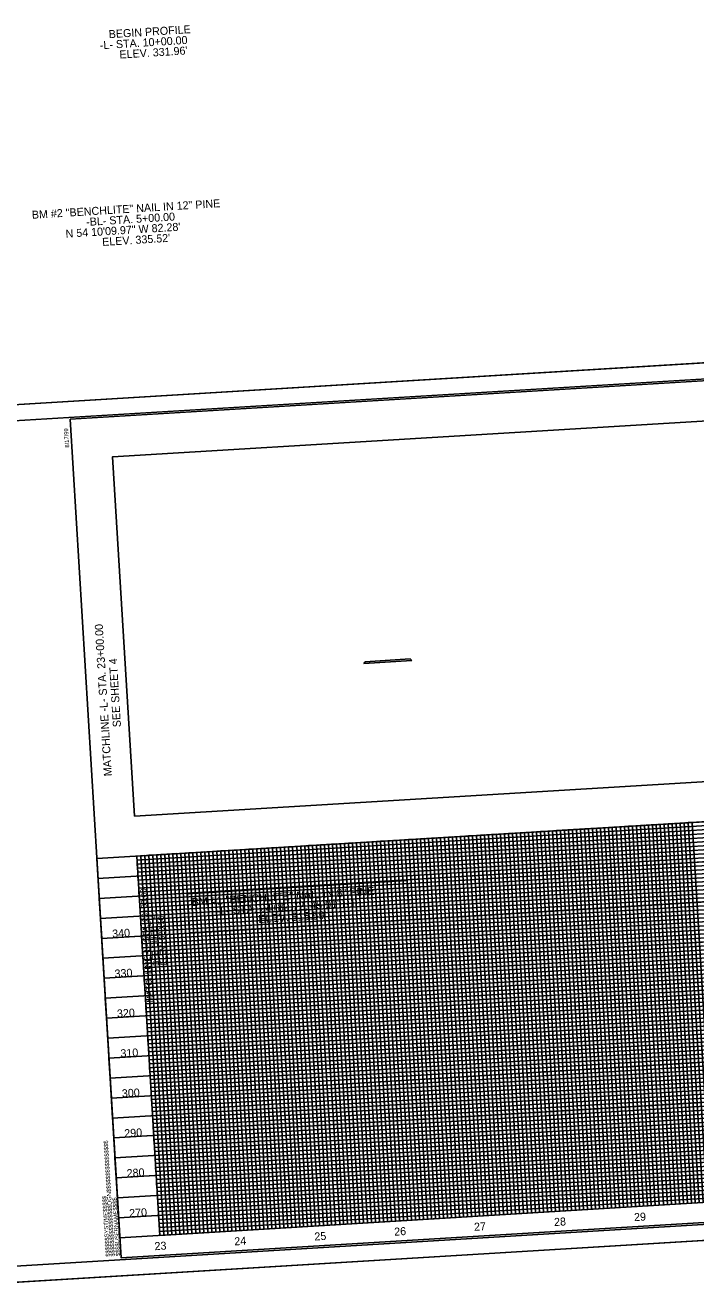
# Model space of a CAD drawing. Extents: x 2111349 to 2114115, y 669753 to 671326.
# Drawn here: x 2112280 to 2113118, y 669753 to 671326 of the extents above; entities that cross this region are included whole.
import ezdxf

# ---------------------------------------------------------------- set-up
doc = ezdxf.new("R2010")
doc.units = 0
for name, color, linetype in [('Default Symbol Cogo Number', 7, 'Continuous'), ('Exist Building', 7, 'Continuous'), ('Exist Building Leader', 7, 'Continuous'), ('Exist Guardrail', 7, 'Continuous'), ('Exist Other Culture Area Outline', 7, 'Continuous'), ('Exist Other Culture Area Outline Text', 7, 'Continuous'), ('Exist Other Culture Sign Leader', 7, 'Continuous'), ('Exist Roads Curbs', 7, 'Continuous'), ('Exist Roads Curbs Text', 7, 'Continuous'), ('Exist Roads EOP Other Text', 7, 'Continuous'), ('Exist Roads EOP Text', 7, 'Continuous'), ('Exist Roads Soil', 7, 'Continuous'), ('Exist Structure Minor Catch Basin', 7, 'Continuous'), ('Exist Structure Minor Footbridge', 7, 'Continuous'), ('Exist Structure Minor Pipes CMP 60 Inch', 7, 'Continuous'), ('Exist Utilities TV Hand Hole CELL', 7, 'Continuous'), ('Exist Utilities TV Test Hole SUE LOS A Text', 7, 'Continuous'), ('Exist Utilities Water Test Hole SUE LOS A Text', 7, 'Continuous')]:
    doc.layers.add(name, color=color, linetype=linetype)

msp = doc.modelspace()

# ---------------------------------------------------------------- linework, layer by layer
at = {"layer": 'Default Symbol Cogo Number'}
for p, q in [((2112763, 670531.9), (2112703, 670528)), ((2112703, 670528), (2112763, 670531.9)), ((2112703, 670528), (2112704.7, 670530.1)), ((2112704.7, 670530.1), (2112703, 670528)), ((2112761.2, 670533.8), (2112704.7, 670530.1)), ((2112761.2, 670533.8), (2112704.7, 670530.1)), ((2112761.2, 670533.8), (2112763, 670531.9)), ((2112763, 670531.9), (2112761.2, 670533.8))]:
    msp.add_line(p, q, dxfattribs=at)
at = {"layer": 'Exist Building'}
for points in [[(2112369.7, 670284.3), (2113867, 670375.1)], [(2113870, 670325.2), (2112372.8, 670234.4), (2112375.8, 670184.5), (2113873, 670275.3)], [(2112947.5, 669843.5), (2112918.7, 670317.6), (2112968.6, 670320.6), (2112997.4, 669846.5)], [(2113047.3, 669849.5), (2113018.5, 670323.6), (2113068.4, 670326.7), (2113097.2, 669852.5)], [(2112648, 669825.3), (2112619.3, 670299.4), (2112669.2, 670302.5), (2112697.9, 669828.3)], [(2112747.8, 669831.4), (2112719.1, 670305.5), (2112769, 670308.5), (2112797.7, 669834.4)], [(2112847.6, 669837.4), (2112818.9, 670311.5), (2112868.8, 670314.6), (2112897.5, 669840.4)], [(2112448.4, 669813.2), (2112419.6, 670287.4), (2112469.5, 670290.4), (2112498.3, 669816.2)], [(2112548.2, 669819.3), (2112519.5, 670293.4), (2112569.4, 670296.4), (2112598.1, 669822.3)], [(2112369.7, 670284.3), (2112398.5, 669810.2)], [(2113876.1, 670225.3), (2112378.8, 670134.6), (2112381.8, 670084.7), (2113879.1, 670175.4)], [(2113882.1, 670125.5), (2112384.9, 670034.8), (2112387.9, 669984.9), (2113885.1, 670075.6)], [(2113888.2, 670025.7), (2112390.9, 669935), (2112393.9, 669885.1), (2113891.2, 669975.8)], [(2113894.2, 669925.9), (2112396.9, 669835.1)]]:
    msp.add_lwpolyline(points, dxfattribs=at)
at = {"layer": 'Exist Building Leader'}
for points in [[(2113817.4, 670367.1), (2112419.9, 670282.4)], [(2113818, 670357.1), (2112420.5, 670272.4), (2112420.2, 670277.4), (2113817.7, 670362.1)], [(2113818.9, 670342.1), (2112421.5, 670257.4), (2112421.1, 670262.4), (2112420.8, 670267.4), (2113818.3, 670352.1)], [(2113819.5, 670332.1), (2112422.1, 670247.4), (2112421.8, 670252.4), (2113819.2, 670337.1)], [(2113820.4, 670317.1), (2112423, 670232.5), (2112422.7, 670237.4), (2112422.4, 670242.4), (2113819.8, 670327.1)], [(2112952.4, 669843.8), (2112923.7, 670317.9), (2112928.7, 670318.2), (2112957.4, 669844.1)], [(2112962.4, 669844.4), (2112933.7, 670318.5), (2112938.7, 670318.8), (2112967.4, 669844.7)], [(2112977.4, 669845.3), (2112948.7, 670319.4), (2112953.7, 670319.7), (2112982.4, 669845.6)], [(2112987.4, 669845.9), (2112958.6, 670320), (2112963.6, 670320.3), (2112992.4, 669846.2)], [(2113002.4, 669846.8), (2112973.6, 670320.9), (2112978.6, 670321.2), (2113007.3, 669847.1)], [(2113012.3, 669847.4), (2112983.6, 670321.5), (2112988.6, 670321.8), (2113017.3, 669847.7)], [(2113027.3, 669848.3), (2112998.6, 670322.4), (2113003.6, 670322.7), (2113032.3, 669848.6)], [(2113037.3, 669848.9), (2113008.6, 670323), (2113013.5, 670323.3), (2113042.3, 669849.2)], [(2113052.3, 669849.8), (2113023.5, 670323.9), (2113028.5, 670324.3), (2113057.3, 669850.1)], [(2113062.2, 669850.4), (2113033.5, 670324.6), (2113038.5, 670324.9), (2113067.2, 669850.7)], [(2113077.2, 669851.3), (2113048.5, 670325.5), (2113053.5, 670325.8), (2113082.2, 669851.6)], [(2113087.2, 669851.9), (2113058.5, 670326.1), (2113063.5, 670326.4), (2113092.2, 669852.2)], [(2113102.2, 669852.8), (2113073.4, 670327), (2113078.4, 670327.3), (2113107.2, 669853.1)], [(2113112.2, 669853.4), (2113083.4, 670327.6), (2113088.4, 670327.9), (2113117.1, 669853.8)], [(2113127.1, 669854.4), (2113098.4, 670328.5), (2113103.4, 670328.8), (2113132.1, 669854.7)], [(2113137.1, 669855), (2113108.4, 670329.1), (2113113.4, 670329.4), (2113142.1, 669855.3)], [(2113821, 670307.2), (2112423.6, 670222.5), (2112423.3, 670227.5), (2113820.7, 670312.2)], [(2113821.9, 670292.2), (2112424.5, 670207.5), (2112424.2, 670212.5), (2112423.9, 670217.5), (2113821.3, 670302.2)], [(2112687.9, 669827.7), (2112659.2, 670301.9), (2112664.2, 670302.2), (2112692.9, 669828)], [(2112702.9, 669828.6), (2112674.2, 670302.8), (2112679.2, 670303.1), (2112707.9, 669828.9)], [(2112712.9, 669829.3), (2112684.2, 670303.4), (2112689.1, 670303.7), (2112717.9, 669829.6)], [(2112727.9, 669830.2), (2112699.1, 670304.3), (2112704.1, 670304.6), (2112732.8, 669830.5)], [(2112737.8, 669830.8), (2112709.1, 670304.9), (2112714.1, 670305.2), (2112742.8, 669831.1)], [(2112752.8, 669831.7), (2112724.1, 670305.8), (2112729.1, 670306.1), (2112757.8, 669832)], [(2112762.8, 669832.3), (2112734.1, 670306.4), (2112739, 670306.7), (2112767.8, 669832.6)], [(2112777.8, 669833.2), (2112749, 670307.3), (2112754, 670307.6), (2112782.8, 669833.5)], [(2112787.7, 669833.8), (2112759, 670307.9), (2112764, 670308.2), (2112792.7, 669834.1)], [(2112802.7, 669834.7), (2112774, 670308.8), (2112779, 670309.1), (2112807.7, 669835)], [(2112812.7, 669835.3), (2112784, 670309.4), (2112789, 670309.7), (2112817.7, 669835.6)], [(2112827.7, 669836.2), (2112798.9, 670310.3), (2112803.9, 670310.6), (2112832.7, 669836.5)], [(2112837.7, 669836.8), (2112808.9, 670310.9), (2112813.9, 670311.2), (2112842.6, 669837.1)], [(2112852.6, 669837.7), (2112823.9, 670311.9), (2112828.9, 670312.2), (2112857.6, 669838)], [(2112862.6, 669838.3), (2112833.9, 670312.5), (2112838.9, 670312.8), (2112867.6, 669838.6)], [(2112877.6, 669839.2), (2112848.8, 670313.4), (2112853.8, 670313.7), (2112882.6, 669839.5)], [(2112887.6, 669839.8), (2112858.8, 670314), (2112863.8, 670314.3), (2112892.6, 669840.1)], [(2112902.5, 669840.7), (2112873.8, 670314.9), (2112878.8, 670315.2), (2112907.5, 669841)], [(2112912.5, 669841.4), (2112883.8, 670315.5), (2112888.8, 670315.8), (2112917.5, 669841.7)], [(2112927.5, 669842.3), (2112898.8, 670316.4), (2112903.7, 670316.7), (2112932.5, 669842.6)], [(2112937.5, 669842.9), (2112908.7, 670317), (2112913.7, 670317.3), (2112942.5, 669843.2)], [(2112453.4, 669813.5), (2112424.6, 670287.7), (2112429.6, 670288), (2112458.4, 669813.8)], [(2113822.5, 670282.2), (2112425.1, 670197.5), (2112424.8, 670202.5), (2113822.2, 670287.2)], [(2112463.3, 669814.1), (2112434.6, 670288.3), (2112439.6, 670288.6), (2112468.3, 669814.4)], [(2112478.3, 669815), (2112449.6, 670289.2), (2112454.6, 670289.5), (2112483.3, 669815.3)], [(2112488.3, 669815.6), (2112459.6, 670289.8), (2112464.6, 670290.1), (2112493.3, 669815.9)], [(2112503.3, 669816.5), (2112474.5, 670290.7), (2112479.5, 670291), (2112508.3, 669816.8)], [(2112513.3, 669817.2), (2112484.5, 670291.3), (2112489.5, 670291.6), (2112518.2, 669817.5)], [(2112528.2, 669818.1), (2112499.5, 670292.2), (2112504.5, 670292.5), (2112533.2, 669818.4)], [(2112538.2, 669818.7), (2112509.5, 670292.8), (2112514.5, 670293.1), (2112543.2, 669819)], [(2112553.2, 669819.6), (2112524.4, 670293.7), (2112529.4, 670294), (2112558.2, 669819.9)], [(2112563.2, 669820.2), (2112534.4, 670294.3), (2112539.4, 670294.6), (2112568.2, 669820.5)], [(2112578.1, 669821.1), (2112549.4, 670295.2), (2112554.4, 670295.5), (2112583.1, 669821.4)], [(2112588.1, 669821.7), (2112559.4, 670295.8), (2112564.4, 670296.1), (2112593.1, 669822)], [(2112603.1, 669822.6), (2112574.4, 670296.7), (2112579.3, 670297), (2112608.1, 669822.9)], [(2112613.1, 669823.2), (2112584.3, 670297.3), (2112589.3, 670297.6), (2112618.1, 669823.5)], [(2112628, 669824.1), (2112599.3, 670298.2), (2112604.3, 670298.5), (2112633, 669824.4)], [(2112638, 669824.7), (2112609.3, 670298.8), (2112614.3, 670299.1), (2112643, 669825)], [(2112653, 669825.6), (2112624.3, 670299.8), (2112629.3, 670300.1), (2112658, 669825.9)], [(2112663, 669826.2), (2112634.2, 670300.4), (2112639.2, 670300.7), (2112668, 669826.5)], [(2112677.9, 669827.1), (2112649.2, 670301.3), (2112654.2, 670301.6), (2112682.9, 669827.4)], [(2112426, 670182.5), (2112425.7, 670187.5), (2112425.4, 670192.5), (2113822.8, 670277.2)], [(2113823.7, 670262.2), (2112426.3, 670177.6), (2112426, 670182.5), (2113823.4, 670267.2)], [(2113824.3, 670252.3), (2112426.9, 670167.6), (2112426.6, 670172.6), (2113824, 670257.3)], [(2113825.2, 670237.3), (2112427.8, 670152.6), (2112427.5, 670157.6), (2113824.9, 670242.3)], [(2113825.8, 670227.3), (2112428.4, 670142.6), (2112428.1, 670147.6), (2113825.5, 670232.3)], [(2113826.8, 670212.3), (2112429.3, 670127.6), (2112429, 670132.6), (2113826.4, 670217.3)], [(2113827.4, 670202.4), (2112429.9, 670117.7), (2112429.6, 670122.7), (2113827.1, 670207.3)], [(2113828.3, 670187.4), (2112430.8, 670102.7), (2112430.5, 670107.7), (2113828, 670192.4)], [(2113828.9, 670177.4), (2112431.4, 670092.7), (2112431.1, 670097.7), (2113828.6, 670182.4)], [(2113829.8, 670162.4), (2112432.3, 670077.7), (2112432, 670082.7), (2113829.5, 670167.4)], [(2113830.4, 670152.4), (2112432.9, 670067.8), (2112432.6, 670072.7), (2113830.1, 670157.4)], [(2113831.3, 670137.5), (2112433.9, 670052.8), (2112433.5, 670057.8), (2113831, 670142.5)], [(2113831.9, 670127.5), (2112434.5, 670042.8), (2112434.2, 670047.8), (2113831.6, 670132.5)], [(2113832.8, 670112.5), (2112435.4, 670027.8), (2112435.1, 670032.8), (2113832.5, 670117.5)], [(2113833.4, 670102.5), (2112436, 670017.8), (2112435.7, 670022.8), (2113833.1, 670107.5)], [(2113834.3, 670087.6), (2112436.9, 670002.9), (2112436.6, 670007.9), (2113834, 670092.6)], [(2113834.9, 670077.6), (2112437.5, 669992.9), (2112437.2, 669997.9), (2113834.6, 670082.6)], [(2113835.8, 670062.6), (2112438.4, 669977.9), (2112438.1, 669982.9), (2113835.5, 670067.6)], [(2113836.4, 670052.6), (2112439, 669967.9), (2112438.7, 669972.9), (2113836.1, 670057.6)], [(2113837.3, 670037.7), (2112439.9, 669953), (2112439.6, 669958), (2113837, 670042.6)], [(2113837.9, 670027.7), (2112440.5, 669943), (2112440.2, 669948), (2113837.6, 670032.7)], [(2113838.8, 670012.7), (2112441.4, 669928), (2112441.1, 669933), (2113838.5, 670017.7)], [(2113839.5, 670002.7), (2112442, 669918), (2112441.7, 669923), (2113839.2, 670007.7)], [(2113840.4, 669987.7), (2112442.9, 669903.1), (2112442.6, 669908), (2113840.1, 669992.7)], [(2113841, 669977.8), (2112443.5, 669893.1), (2112443.2, 669898.1), (2113840.7, 669982.8)], [(2112444.4, 669878.1), (2112444.1, 669883.1), (2113841.6, 669967.8)], [(2112448.1, 669818.2), (2113845.5, 669902.9), (2113845.2, 669907.9), (2112447.8, 669823.2), (2112447.5, 669828.2), (2113844.9, 669912.9), (2113844.6, 669917.9), (2112447.2, 669833.2), (2112446.9, 669838.2), (2112446.6, 669843.2), (2113844, 669927.9), (2113843.7, 669932.8), (2112446.3, 669848.2), (2112446, 669853.1), (2113843.4, 669937.8), (2113843.1, 669942.8), (2112445.6, 669858.1), (2112445.3, 669863.1), (2112445, 669868.1), (2113842.5, 669952.8), (2113842.2, 669957.8), (2112444.7, 669873.1), (2112444.4, 669878.1), (2113841.9, 669962.8)]]:
    msp.add_lwpolyline(points, dxfattribs=at)
at = {"layer": 'Exist Other Culture Area Outline'}
for p, q in [((2112371.2, 670259.4), (2113868.5, 670350.1)), ((2113871.5, 670300.2), (2112374.3, 670209.5)), ((2112377.3, 670159.6), (2113874.5, 670250.3)), ((2112374.3, 670209.5), (2112377.3, 670159.6)), ((2113877.6, 670200.4), (2112380.3, 670109.6)), ((2112383.3, 670059.7), (2113880.6, 670150.5)), ((2112380.3, 670109.6), (2112383.3, 670059.7)), ((2113883.6, 670100.6), (2112386.4, 670009.8)), ((2112389.4, 669959.9), (2113886.6, 670050.7)), ((2112386.4, 670009.8), (2112389.4, 669959.9)), ((2113889.7, 670000.8), (2112392.4, 669910)), ((2112395.4, 669860.1), (2113892.7, 669950.8)), ((2112392.4, 669910), (2112395.4, 669860.1))]:
    msp.add_line(p, q, dxfattribs=at)
for points in [[(2112972.4, 669845), (2112943.7, 670319.1), (2112993.6, 670322.1), (2113022.3, 669848)], [(2113072.2, 669851), (2113043.5, 670325.2), (2113093.4, 670328.2), (2113122.1, 669854.1)], [(2112673, 669826.8), (2112644.2, 670301), (2112694.1, 670304), (2112722.9, 669829.9)], [(2112772.8, 669832.9), (2112744, 670307), (2112793.9, 670310), (2112822.7, 669835.9)], [(2112872.6, 669838.9), (2112843.9, 670313.1), (2112893.8, 670316.1), (2112922.5, 669842)], [(2112473.3, 669814.7), (2112444.6, 670288.9), (2112494.5, 670291.9), (2112523.2, 669817.8)], [(2112573.1, 669820.8), (2112544.4, 670294.9), (2112594.3, 670297.9), (2112623.1, 669823.8)]]:
    msp.add_lwpolyline(points, dxfattribs=at)
at = {"layer": 'Exist Other Culture Area Outline Text'}
msp.add_lwpolyline([(2112455.6, 670189.3), (2112425.7, 670187.5), (2112431.6, 670090.4)], dxfattribs=at)
at = {"layer": 'Exist Other Culture Sign Leader'}
msp.add_lwpolyline([(2112419.6, 670287.4), (2113817.1, 670372), (2113845.8, 669897.9), (2112448.4, 669813.2)], close=True, dxfattribs=at)
at = {"layer": 'Exist Roads Curbs'}
for p, q in [((2113849.3, 670947.5), (2112168.9, 670845.7)), ((2112235.1, 669752.7), (2113915.6, 669854.6))]:
    msp.add_line(p, q, dxfattribs=at)
at = {"layer": 'Exist Roads Curbs Text'}
for p, q in [((2113895.7, 669900.9), (2112398.5, 669810.2)), ((2112400, 669785.2), (2112400, 669785.2)), ((2112400, 669785.2), (2112400, 669785.2)), ((2112400, 669785.2), (2112400, 669785.2)), ((2112400, 669785.2), (2112400, 669785.2)), ((2112400, 669785.2), (2112400, 669785.2))]:
    msp.add_line(p, q, dxfattribs=at)
msp.add_lwpolyline([(2113833.7, 670924.1), (2112336.5, 670833.3), (2112400, 669785.2), (2113897.2, 669876)], close=True, dxfattribs=at)
at = {"layer": 'Exist Roads EOP Other Text'}
msp.add_lwpolyline([(2112246.9, 669773.5), (2113909.9, 669874.2), (2113846, 670927.3), (2112183.1, 670826.5)], close=True, dxfattribs=at)
at = {"layer": 'Exist Roads Soil'}
msp.add_line((2112400, 669785.2), (2112400, 669785.2), dxfattribs=at)
at = {"layer": 'Exist Structure Minor Catch Basin'}
msp.add_line((2112416.6, 670337.3), (2112389.4, 670786.4), dxfattribs=at)
at = {"layer": 'Exist Structure Minor Pipes CMP 60 Inch'}
msp.add_lwpolyline([(2112482.6, 670240.1), (2112757.1, 670256.7), (2112760.1, 670207.8), (2112485.6, 670191.2)], close=True, dxfattribs=at)
at = {"layer": 'Exist Utilities TV Hand Hole CELL'}
for p, q in [((2112369.7, 670284.3), (2113867, 670375.1)), ((2112372.8, 670234.4), (2113870, 670325.2)), ((2112918.7, 670317.6), (2112947.5, 669843.5)), ((2112968.6, 670320.6), (2112997.4, 669846.5)), ((2113018.5, 670323.6), (2113047.3, 669849.5)), ((2113068.4, 670326.7), (2113097.2, 669852.5)), ((2112669.2, 670302.5), (2112697.9, 669828.3)), ((2112719.1, 670305.5), (2112747.8, 669831.4)), ((2112769, 670308.5), (2112797.7, 669834.4)), ((2112818.9, 670311.5), (2112847.6, 669837.4)), ((2112868.8, 670314.6), (2112897.5, 669840.4)), ((2112419.6, 670287.4), (2112448.4, 669813.2)), ((2112469.5, 670290.4), (2112498.3, 669816.2)), ((2112519.5, 670293.4), (2112548.2, 669819.3)), ((2112569.4, 670296.4), (2112598.1, 669822.3)), ((2112619.3, 670299.4), (2112648, 669825.3)), ((2112375.8, 670184.5), (2113873, 670275.3)), ((2112378.8, 670134.6), (2113876.1, 670225.3)), ((2112381.8, 670084.7), (2113879.1, 670175.4)), ((2112384.9, 670034.8), (2113882.1, 670125.5)), ((2112387.9, 669984.9), (2113885.1, 670075.6)), ((2112390.9, 669935), (2113888.2, 670025.7)), ((2112393.9, 669885.1), (2113891.2, 669975.8)), ((2112396.9, 669835.1), (2113894.2, 669925.9))]:
    msp.add_line(p, q, dxfattribs=at)
at = {"layer": 'Exist Utilities TV Test Hole SUE LOS A Text'}
msp.add_lwpolyline([(2112416.6, 670337.3), (2112389.4, 670786.4), (2113587.1, 670859), (2113596.2, 670709.3), (2113795.9, 670721.4), (2113814, 670422)], close=True, dxfattribs=at)
at = {"layer": 'Exist Utilities Water Test Hole SUE LOS A Text'}
msp.add_lwpolyline([(2112235.1, 669752.7), (2113915.6, 669854.6), (2113849.3, 670947.5), (2112168.9, 670845.7)], close=True, dxfattribs=at)

# ---------------------------------------------------------------- texts
at = {"layer": 'Exist Guardrail'}
for s, p in [('340', (2112389.2, 670185.3)), ('330', (2112392.2, 670135.4)), ('320', (2112395.2, 670085.5)), ('310', (2112399.5, 670035.7)), ('300', (2112401.3, 669985.7)), ('290', (2112404.3, 669935.8)), ('280', (2112407.3, 669885.9)), ('270', (2112410.4, 669836))]:
    msp.add_text(s, height=10, rotation=3.4682, dxfattribs=at).set_placement(p)
at = {"layer": 'Exist Other Culture Area Outline Text'}
for s, height, rotation, p in [('  BEGIN PROFILE', 10, 3.552, (2112377.5, 671309.1)), ('    -L- STA. 10+00.00', 10, 3.552, (2112359, 671294.8)), ("ELEV. 331.96'", 10, 3.552, (2112398.3, 671284.1)), ('BM #2 "BENCHLITE" NAIL IN 12" PINE', 10, 3.552, (2112288.9, 671083.8)), ('-BL- STA. 5+00.00', 10, 3.552, (2112356.7, 671074.9)), ('N 54 10\'09.97" W 82.28\'', 10, 3.552, (2112331, 671060.2)), ("ELEV. 335.52'", 10, 3.552, (2112376.7, 671049.9)), ('MATCHLINE -L- STA. 23+00.00', 7.5, 93.4682, (2112440.1, 670104.4)), ('BM #1 "BENCHLITE" NAIL IN 8" PINE', 10, 3.552, (2112488.7, 670224.7)), ("-L- STA. 24+82.72, 45.91' RT", 10, 3.552, (2112519.8, 670213.5)), ('SEE SHEET 4 ', 7.5, 93.4682, (2112447.2, 670150.3)), ('ELEV. 320.58', 7.5, 93.4682, (2112457, 670151)), ("ELEV. 315.59'", 10, 3.552, (2112571.8, 670203.6))]:
    msp.add_text(s, height=height, rotation=rotation, dxfattribs=at).set_placement(p)
at = {"layer": 'Exist Roads Curbs Text'}
msp.add_text('8/17/99', height=5.25, rotation=93.4682, dxfattribs=at).set_placement((2112335.3, 670798))
at = {"layer": 'Exist Roads EOP Text'}
for s, p in [('MATCHLINE -L- STA. 23+00.00', (2112388.6, 670387.4)), ('SEE SHEET 4', (2112399.9, 670448.7))]:
    msp.add_text(s, height=10, rotation=93.4682, dxfattribs=at).set_placement(p)
at = {"layer": 'Exist Roads Soil'}
for s, p in [('$$$$$$$$$$$$$$$$DGN$$$$$$$$$$$$$$$$', (2112392.2, 669787.1)), ('$$$$$$SYSTIME$$$$$', (2112386.2, 669786.8)), ('$$$$USERNAME$$$$', (2112398.8, 669787.5))]:
    msp.add_text(s, height=5.25, rotation=93.4682, dxfattribs=at).set_placement(p)
at = {"layer": 'Exist Structure Minor Footbridge'}
for s, p in [('27', (2112841.1, 669818.9)), ('28', (2112941, 669824.9)), ('29', (2113040.9, 669831)), ('25', (2112641.7, 669806.8)), ('26', (2112741.4, 669812.8)), ('23', (2112442.1, 669794.7)), ('24', (2112541.7, 669800.7))]:
    msp.add_text(s, height=10, rotation=3.4682, dxfattribs=at).set_placement(p)

doc.saveas('drawing.dxf')
